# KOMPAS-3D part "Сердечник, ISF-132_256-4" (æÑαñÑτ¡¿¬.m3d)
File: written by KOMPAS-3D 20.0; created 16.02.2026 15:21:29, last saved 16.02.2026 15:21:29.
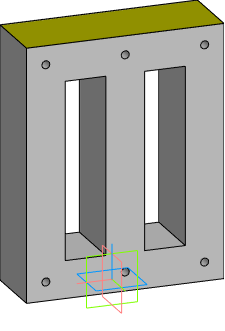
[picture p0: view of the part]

Document properties: Автор: admin; Полное имя файла: P:\INSTART\Технический отдел\ОР\Прочие задачи\КД на номенклатурный ряд\КД на типоразмеры дросселей\Сетевые дроссели ISF\ISF-4\Тип 1\ISF-132_256-4\0723\Новая папка\Сердечник.m3d

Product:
- Part/product: Сердечник  | designation ISF-132_256-4

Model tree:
1. Операция без истории:1
2. Операция без истории:2

Expressions: ISF-132_256-4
